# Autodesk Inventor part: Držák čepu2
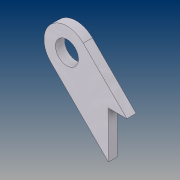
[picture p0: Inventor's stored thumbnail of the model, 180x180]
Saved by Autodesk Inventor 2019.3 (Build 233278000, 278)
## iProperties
Created: 2019-03
Part Number: Držák čepu2
Material: Ocel, měkká, svařovaná
Document SubType Name: Modeling
Designer: B-hon
Density: 7.85 g/cm^3
Appearance: Svar – hliník
Author: B-hon
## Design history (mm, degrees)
sketch "Náčrt1"
  geometry: L1 (10.607, 10.607)-(27, -5.787); L2 (27, -48.213)-(-10.607, -10.607); L3 (27, -48.213)-(27, -5.787); L4 (0, 0)-(42.179, 0); C1 r 7.5 at (0, 0); A1 r 15 centre (0, 0) between (10.607, 10.607) and (-10.607, -10.607); 1 further point
  constraints: 8 end point, 2 centre point, 2 coincident, 2 point on circle, 2 tangent, 1 horizontal, 1 vertical
  dimensions: "d0" = 30 diameter of A1; "d1" = 15 diameter of C1; "d3" = 0 deg angle of L1 L2; "d6" = 45 deg angle of L4 L2; "d7" = 27 distance from line of L3 point (0, 0)
extrude "Vysunutí1" new body sketch "Náčrt1" distance "d4" = 6; taper "d5" = 0 deg
sketch "Náčrt2"
  geometry: L1 (27, -48.213)-(27, -5.787) reference; L2 (27, -5.787)-(39, -17.787); L3 (39, -17.787)-(27, -17.787); L4 (27, -5.787)-(10.607, 10.607) reference; L5 (27, -5.787)-(27, -17.787); 1 further point
  constraints: 6 end point, 2 collinear, 1 horizontal, 1 point on line
  dimensions: "d8" = 12 distance of L2.end L3.end
extrude "Vysunutí2" join sketch "Náčrt2" distance "d9" = 6; taper "d10" = 0 deg
node "Těleso1"
